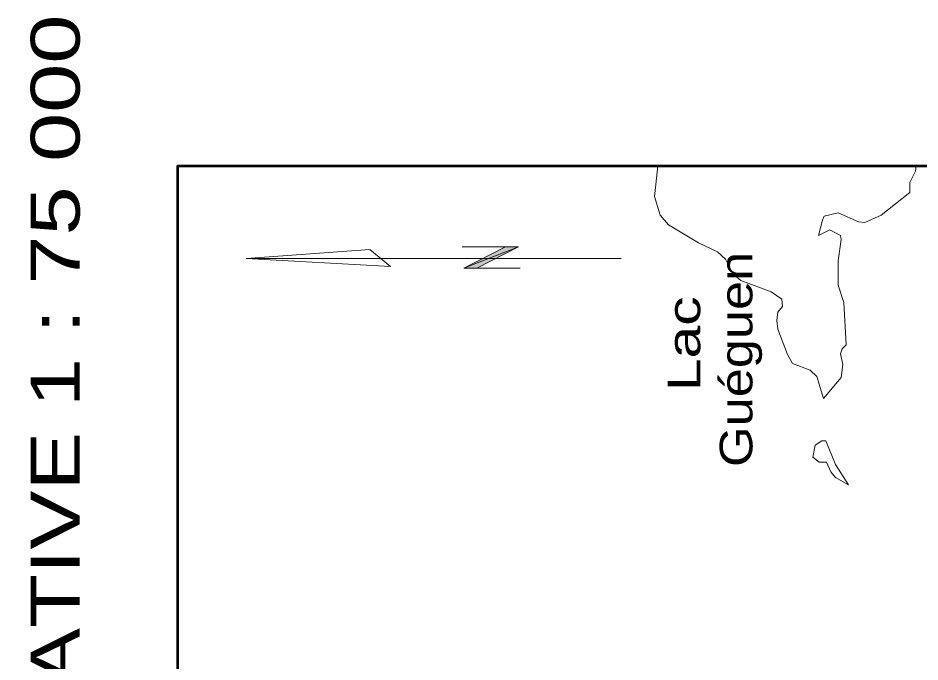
# Model space of a CAD drawing. Extents: x 240591 to 242335, y 5323482 to 5326937.
# Drawn here: x 241431.3 to 241542, y 5326681.1 to 5326760.1 of the extents above; entities that cross this region are included whole.
import ezdxf
from ezdxf.enums import TextEntityAlignment as Align

# ---------------------------------------------------------------- set-up
doc = ezdxf.new("R2010")
doc.units = 0
doc.header["$LTSCALE"] = 1.2
doc.layers.add('63', color=7, linetype='Continuous', lineweight=13)

msp = doc.modelspace()

# ---------------------------------------------------------------- hatches: boundary and pattern name
at = {"layer": '63'}
msp.add_hatch(color=256, dxfattribs=at).paths.add_polyline_path([(241492.7, 5326732), (241487.6, 5326729.4), (241486, 5326729.4), (241491.1, 5326732)])

# ---------------------------------------------------------------- linework, layer by layer
msp.add_line((241509.4, 5326738.2), (241509.8, 5326741.9), dxfattribs=at)
at = {"layer": '63', "lineweight": 53}
msp.add_lwpolyline([(241606.9, 5326533.9), (241606.9, 5326741.9), (241450.9, 5326741.9), (241450.9, 5326533.9)], close=True, dxfattribs=at)
at = {"layer": '63'}
for points in [[(241541.5, 5326741.9), (241509.8, 5326741.9), (241509.4, 5326738.2), (241510.1, 5326735.9), (241511.1, 5326734.7), (241514.8, 5326732.5), (241517.1, 5326731.4), (241518.1, 5326730.5), (241519, 5326728.7), (241520, 5326727.9), (241523.7, 5326726.5), (241525, 5326725.6), (241525.1, 5326724.7), (241524.5, 5326724), (241524.4, 5326723), (241524.5, 5326721.9), (241525.7, 5326718.8), (241526.3, 5326717.7), (241528.5, 5326716.9), (241529.3, 5326716.1), (241530.1, 5326713.4), (241532.3, 5326716), (241532.5, 5326717.6), (241532.2, 5326718.9), (241532.4, 5326719.5), (241532.9, 5326720), (241532.6, 5326725.2), (241531.9, 5326727.3), (241531.9, 5326730.3), (241532.3, 5326732.9), (241532.2, 5326733.4), (241530.9, 5326734.1), (241529.5, 5326733.4), (241530, 5326735.3), (241530.2, 5326735.8), (241531.9, 5326736.2), (241534.4, 5326735.1), (241535.2, 5326735), (241537.2, 5326735.9), (241540.7, 5326738.7), (241540.7, 5326739.9), (241541.4, 5326741.3)], [(241477, 5326729.6), (241459.3, 5326730.6), (241474.5, 5326731.7)], [(241492.7, 5326732), (241487.6, 5326729.4), (241486, 5326729.4), (241491.1, 5326732)], [(241529.9, 5326708.2), (241529.1, 5326707.7), (241528.8, 5326706.2), (241529.6, 5326705.6), (241530.5, 5326705.6), (241531, 5326704.4), (241531.6, 5326703.7), (241533.2, 5326702.8), (241531.6, 5326705.3), (241530.4, 5326708.2)]]:
    msp.add_lwpolyline(points, close=True, dxfattribs=at)
for points in [[(241530.1, 5326713.4), (241532.3, 5326716), (241532.5, 5326717.6), (241532.2, 5326718.9), (241532.4, 5326719.5), (241532.9, 5326720), (241532.6, 5326725.2), (241531.9, 5326727.3), (241531.9, 5326730.3), (241532.3, 5326732.9), (241532.2, 5326733.4), (241530.9, 5326734.1), (241529.5, 5326733.4), (241530, 5326735.3), (241530.2, 5326735.8), (241531.9, 5326736.2), (241534.4, 5326735.1), (241535.2, 5326735), (241537.2, 5326735.9), (241540.7, 5326738.7), (241540.7, 5326739.9), (241541.4, 5326741.3), (241541.5, 5326741.9)], [(241530.1, 5326713.4), (241529.3, 5326716.1), (241528.5, 5326716.9), (241526.3, 5326717.7), (241525.7, 5326718.8), (241524.5, 5326721.9), (241524.4, 5326723), (241524.5, 5326724), (241525.1, 5326724.7), (241525, 5326725.6), (241523.7, 5326726.5), (241520, 5326727.9), (241519, 5326728.7), (241518.1, 5326730.5), (241517.1, 5326731.4), (241514.8, 5326732.5), (241511.1, 5326734.7), (241510.1, 5326735.9), (241509.4, 5326738.2)], [(241492.9, 5326729.4), (241486, 5326729.4), (241492.7, 5326732), (241485.8, 5326732)], [(241505.3, 5326730.6), (241475.8, 5326730.6), (241459.3, 5326730.6)], [(241533.2, 5326702.8), (241531.6, 5326705.3), (241530.4, 5326708.2), (241529.9, 5326708.2), (241529.1, 5326707.7)], [(241533.2, 5326702.8), (241531.6, 5326703.7), (241531, 5326704.4), (241530.5, 5326705.6), (241529.6, 5326705.6), (241528.8, 5326706.2), (241529.1, 5326707.7)]]:
    msp.add_lwpolyline(points, dxfattribs=at)

# ---------------------------------------------------------------- texts
at = {"layer": '63', "width": 1.35}
msp.add_text('ÉCHELLE APPROXIMATIVE 1 : 75 000', height=6, rotation=90, dxfattribs=at).set_placement((241438.9, 5326664.5), align=Align.CENTER)
at = {"layer": '63'}
for s, width, p in [('Guéguen', 1.2, (241521.4, 5326705)), ('Lac ', 1.35, (241515, 5326714.3))]:
    msp.add_text(s, height=4, rotation=90, dxfattribs=dict(at, width=width)).set_placement(p)

doc.saveas('drawing.dxf')
